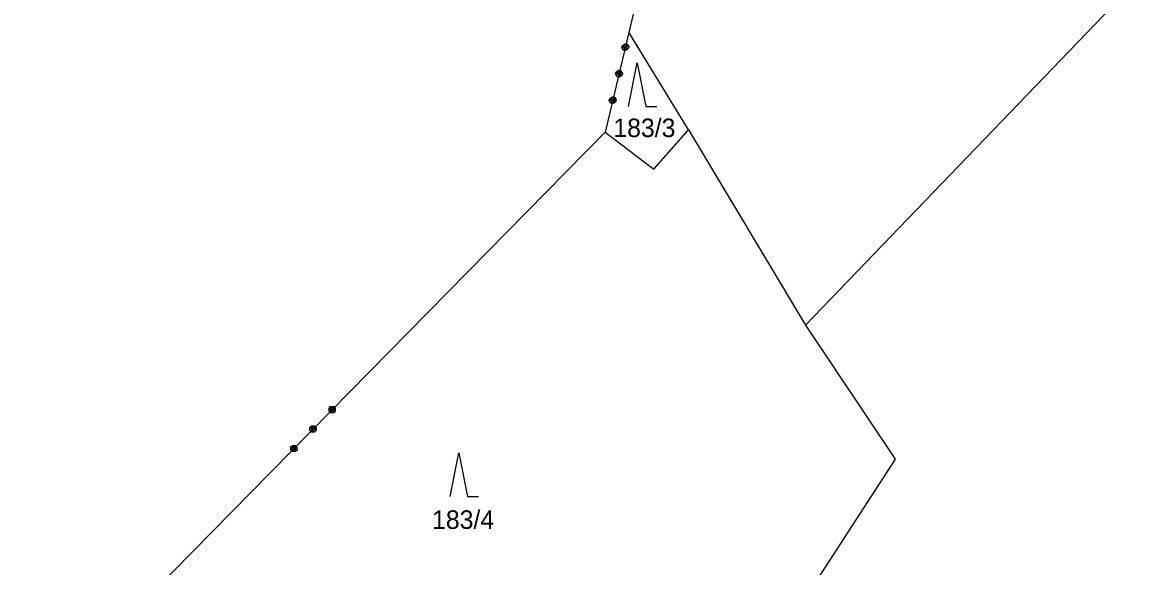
# Model space of a CAD drawing. Extents: x -866656 to -858817, y -1041816 to -1038653.
# Drawn here: x -864815.7 to -864712.3, y -1041085.8 to -1041035.9 of the extents above; entities that cross this region are included whole.
import ezdxf

# ---------------------------------------------------------------- set-up
doc = ezdxf.new("R2010")
doc.units = 0
doc.layers.add('Vrstva 1', color=7, linetype='Continuous')
doc.layers.add('Vrstva 3', color=7, linetype='Continuous')

msp = doc.modelspace()

# ---------------------------------------------------------------- linework, layer by layer
at = {"layer": 'Vrstva 1'}
for p, q in [((-864743.95, -1041063.62), (-864712.34, -1041030.74)), ((-864754.65, -1041045.72), (-864760.13, -1041036.76)), ((-864760.16, -1041043.59), (-864759.36, -1041039.59)), ((-864759.36, -1041039.59), (-864758.56, -1041043.59)), ((-864758.56, -1041043.59), (-864757.56, -1041043.59)), ((-864762.31, -1041045.95), (-864757.85, -1041049.32)), ((-864757.85, -1041049.32), (-864754.65, -1041045.72)), ((-864754.65, -1041045.72), (-864743.95, -1041063.62)), ((-864743.95, -1041063.62), (-864735.74, -1041075.92)), ((-864776.51, -1041079.34), (-864775.71, -1041075.34)), ((-864775.71, -1041075.34), (-864774.91, -1041079.34)), ((-864735.74, -1041075.92), (-864746.95, -1041093.22)), ((-864774.91, -1041079.34), (-864773.91, -1041079.34))]:
    msp.add_line(p, q, dxfattribs=at)
at = {"layer": 'Vrstva 3'}
for p, q in [((-864759.71, -1041035.01), (-864762.31, -1041045.95)), ((-864759.71, -1041035.01), (-864762.31, -1041045.95)), ((-864760.77, -1041038.17), (-864760.72, -1041037.98)), ((-864760.77, -1041038.17), (-864760.72, -1041037.98)), ((-864760.62, -1041038.41), (-864760.77, -1041038.17)), ((-864760.62, -1041038.41), (-864760.77, -1041038.17)), ((-864760.72, -1041037.98), (-864760.48, -1041037.83)), ((-864760.72, -1041037.98), (-864760.48, -1041037.83)), ((-864760.67, -1041038.2), (-864760.63, -1041038)), ((-864760.67, -1041038.2), (-864760.63, -1041038)), ((-864760.28, -1041038.29), (-864760.67, -1041038.2)), ((-864760.28, -1041038.29), (-864760.67, -1041038.2)), ((-864760.65, -1041038.1), (-864760.26, -1041038.19)), ((-864760.65, -1041038.1), (-864760.26, -1041038.19)), ((-864760.63, -1041038), (-864760.24, -1041038.09)), ((-864760.63, -1041038), (-864760.24, -1041038.09)), ((-864760.6, -1041038.32), (-864760.4, -1041038.36)), ((-864760.6, -1041038.32), (-864760.4, -1041038.36)), ((-864760.31, -1041037.97), (-864760.51, -1041037.93)), ((-864760.31, -1041037.97), (-864760.51, -1041037.93)), ((-864760.48, -1041037.83), (-864760.29, -1041037.88)), ((-864760.48, -1041037.83), (-864760.29, -1041037.88)), ((-864760.19, -1041038.31), (-864760.43, -1041038.46)), ((-864760.19, -1041038.31), (-864760.43, -1041038.46)), ((-864760.4, -1041038.36), (-864760.28, -1041038.29)), ((-864760.4, -1041038.36), (-864760.28, -1041038.29)), ((-864760.24, -1041038.09), (-864760.31, -1041037.97)), ((-864760.24, -1041038.09), (-864760.31, -1041037.97)), ((-864760.29, -1041037.88), (-864760.14, -1041038.12)), ((-864760.29, -1041037.88), (-864760.14, -1041038.12)), ((-864760.14, -1041038.12), (-864760.19, -1041038.31)), ((-864760.14, -1041038.12), (-864760.19, -1041038.31)), ((-864760.43, -1041038.46), (-864760.62, -1041038.41)), ((-864760.43, -1041038.46), (-864760.62, -1041038.41)), ((-864761.35, -1041040.6), (-864761.3, -1041040.41)), ((-864761.35, -1041040.6), (-864761.3, -1041040.41)), ((-864761.3, -1041040.41), (-864761.06, -1041040.26)), ((-864761.3, -1041040.41), (-864761.06, -1041040.26)), ((-864761.25, -1041040.63), (-864761.2, -1041040.43)), ((-864761.25, -1041040.63), (-864761.2, -1041040.43)), ((-864761.2, -1041040.43), (-864760.82, -1041040.53)), ((-864761.2, -1041040.43), (-864760.82, -1041040.53)), ((-864760.89, -1041040.41), (-864761.08, -1041040.36)), ((-864760.89, -1041040.41), (-864761.08, -1041040.36)), ((-864761.06, -1041040.26), (-864760.87, -1041040.31)), ((-864761.06, -1041040.26), (-864760.87, -1041040.31)), ((-864760.82, -1041040.53), (-864760.89, -1041040.41)), ((-864760.82, -1041040.53), (-864760.89, -1041040.41)), ((-864760.87, -1041040.31), (-864760.72, -1041040.55)), ((-864760.87, -1041040.31), (-864760.72, -1041040.55)), ((-864761.2, -1041040.85), (-864761.35, -1041040.6)), ((-864761.2, -1041040.85), (-864761.35, -1041040.6)), ((-864760.86, -1041040.72), (-864761.25, -1041040.63)), ((-864760.86, -1041040.72), (-864761.25, -1041040.63)), ((-864761.23, -1041040.53), (-864760.84, -1041040.62)), ((-864761.23, -1041040.53), (-864760.84, -1041040.62)), ((-864761.01, -1041040.89), (-864761.2, -1041040.85)), ((-864761.01, -1041040.89), (-864761.2, -1041040.85)), ((-864761.18, -1041040.75), (-864760.98, -1041040.8)), ((-864761.18, -1041040.75), (-864760.98, -1041040.8)), ((-864760.76, -1041040.74), (-864761.01, -1041040.89)), ((-864760.76, -1041040.74), (-864761.01, -1041040.89)), ((-864760.98, -1041040.8), (-864760.86, -1041040.72)), ((-864760.98, -1041040.8), (-864760.86, -1041040.72)), ((-864760.72, -1041040.55), (-864760.76, -1041040.74)), ((-864760.72, -1041040.55), (-864760.76, -1041040.74)), ((-864761.93, -1041043.04), (-864761.88, -1041042.84)), ((-864761.93, -1041043.04), (-864761.88, -1041042.84)), ((-864761.78, -1041043.28), (-864761.93, -1041043.04)), ((-864761.78, -1041043.28), (-864761.93, -1041043.04)), ((-864761.88, -1041042.84), (-864761.64, -1041042.69)), ((-864761.88, -1041042.84), (-864761.64, -1041042.69)), ((-864761.83, -1041043.06), (-864761.78, -1041042.87)), ((-864761.83, -1041043.06), (-864761.78, -1041042.87)), ((-864761.44, -1041043.15), (-864761.83, -1041043.06)), ((-864761.44, -1041043.15), (-864761.83, -1041043.06)), ((-864761.81, -1041042.96), (-864761.42, -1041043.06)), ((-864761.81, -1041042.96), (-864761.42, -1041043.06)), ((-864761.78, -1041042.87), (-864761.39, -1041042.96)), ((-864761.78, -1041042.87), (-864761.39, -1041042.96)), ((-864761.58, -1041043.32), (-864761.78, -1041043.28)), ((-864761.58, -1041043.32), (-864761.78, -1041043.28)), ((-864761.75, -1041043.18), (-864761.56, -1041043.23)), ((-864761.75, -1041043.18), (-864761.56, -1041043.23)), ((-864761.47, -1041042.84), (-864761.66, -1041042.79)), ((-864761.47, -1041042.84), (-864761.66, -1041042.79)), ((-864761.64, -1041042.69), (-864761.44, -1041042.74)), ((-864761.64, -1041042.69), (-864761.44, -1041042.74)), ((-864761.34, -1041043.18), (-864761.58, -1041043.32)), ((-864761.34, -1041043.18), (-864761.58, -1041043.32)), ((-864761.56, -1041043.23), (-864761.44, -1041043.15)), ((-864761.56, -1041043.23), (-864761.44, -1041043.15)), ((-864761.39, -1041042.96), (-864761.47, -1041042.84)), ((-864761.39, -1041042.96), (-864761.47, -1041042.84)), ((-864761.44, -1041042.74), (-864761.3, -1041042.98)), ((-864761.44, -1041042.74), (-864761.3, -1041042.98)), ((-864761.3, -1041042.98), (-864761.34, -1041043.18)), ((-864761.3, -1041042.98), (-864761.34, -1041043.18)), ((-864762.31, -1041045.95), (-864815.68, -1041100.22)), ((-864762.31, -1041045.95), (-864815.68, -1041100.22)), ((-864787.6, -1041071.23), (-864787.46, -1041071.09)), ((-864787.6, -1041071.23), (-864787.46, -1041071.09)), ((-864787.59, -1041071.52), (-864787.6, -1041071.23)), ((-864787.59, -1041071.52), (-864787.6, -1041071.23)), ((-864787.52, -1041071.3), (-864787.38, -1041071.16)), ((-864787.52, -1041071.3), (-864787.38, -1041071.16)), ((-864787.24, -1041071.59), (-864787.52, -1041071.3)), ((-864787.24, -1041071.59), (-864787.52, -1041071.3)), ((-864787.46, -1041071.09), (-864787.17, -1041071.09)), ((-864787.46, -1041071.09), (-864787.17, -1041071.09)), ((-864787.45, -1041071.23), (-864787.17, -1041071.51)), ((-864787.45, -1041071.23), (-864787.17, -1041071.51)), ((-864787.38, -1041071.16), (-864787.1, -1041071.44)), ((-864787.38, -1041071.16), (-864787.1, -1041071.44)), ((-864787.1, -1041071.3), (-864787.24, -1041071.16)), ((-864787.1, -1041071.3), (-864787.24, -1041071.16)), ((-864787.17, -1041071.09), (-864787.03, -1041071.23)), ((-864787.17, -1041071.09), (-864787.03, -1041071.23)), ((-864787.1, -1041071.44), (-864787.1, -1041071.3)), ((-864787.1, -1041071.44), (-864787.1, -1041071.3)), ((-864787.03, -1041071.23), (-864787.03, -1041071.51)), ((-864787.03, -1041071.23), (-864787.03, -1041071.51)), ((-864787.45, -1041071.66), (-864787.59, -1041071.52)), ((-864787.45, -1041071.66), (-864787.59, -1041071.52)), ((-864787.52, -1041071.45), (-864787.38, -1041071.59)), ((-864787.52, -1041071.45), (-864787.38, -1041071.59)), ((-864787.17, -1041071.66), (-864787.45, -1041071.66)), ((-864787.17, -1041071.66), (-864787.45, -1041071.66)), ((-864787.38, -1041071.59), (-864787.24, -1041071.59)), ((-864787.38, -1041071.59), (-864787.24, -1041071.59)), ((-864787.03, -1041071.51), (-864787.17, -1041071.66)), ((-864787.03, -1041071.51), (-864787.17, -1041071.66)), ((-864789.35, -1041073.02), (-864789.21, -1041072.87)), ((-864789.35, -1041073.02), (-864789.21, -1041072.87)), ((-864789.35, -1041073.3), (-864789.35, -1041073.02)), ((-864789.35, -1041073.3), (-864789.35, -1041073.02)), ((-864789.2, -1041073.44), (-864789.35, -1041073.3)), ((-864789.2, -1041073.44), (-864789.35, -1041073.3)), ((-864789.28, -1041073.09), (-864789.14, -1041072.94)), ((-864789.28, -1041073.09), (-864789.14, -1041072.94)), ((-864788.99, -1041073.37), (-864789.28, -1041073.09)), ((-864788.99, -1041073.37), (-864789.28, -1041073.09)), ((-864789.28, -1041073.23), (-864789.13, -1041073.37)), ((-864789.28, -1041073.23), (-864789.13, -1041073.37)), ((-864789.21, -1041072.87), (-864788.93, -1041072.87)), ((-864789.21, -1041072.87), (-864788.93, -1041072.87)), ((-864789.21, -1041073.02), (-864788.92, -1041073.3)), ((-864789.21, -1041073.02), (-864788.92, -1041073.3)), ((-864788.92, -1041073.44), (-864789.2, -1041073.44)), ((-864788.92, -1041073.44), (-864789.2, -1041073.44)), ((-864789.14, -1041072.94), (-864788.85, -1041073.22)), ((-864789.14, -1041072.94), (-864788.85, -1041073.22)), ((-864789.13, -1041073.37), (-864788.99, -1041073.37)), ((-864789.13, -1041073.37), (-864788.99, -1041073.37)), ((-864788.85, -1041073.08), (-864789, -1041072.94)), ((-864788.85, -1041073.08), (-864789, -1041072.94)), ((-864788.93, -1041072.87), (-864788.78, -1041073.01)), ((-864788.93, -1041072.87), (-864788.78, -1041073.01)), ((-864788.78, -1041073.3), (-864788.92, -1041073.44)), ((-864788.78, -1041073.3), (-864788.92, -1041073.44)), ((-864788.85, -1041073.22), (-864788.85, -1041073.08)), ((-864788.85, -1041073.22), (-864788.85, -1041073.08)), ((-864788.78, -1041073.01), (-864788.78, -1041073.3)), ((-864788.78, -1041073.01), (-864788.78, -1041073.3)), ((-864791.1, -1041074.8), (-864790.96, -1041074.66)), ((-864791.1, -1041074.8), (-864790.96, -1041074.66)), ((-864791.1, -1041075.08), (-864791.1, -1041074.8)), ((-864791.1, -1041075.08), (-864791.1, -1041074.8)), ((-864790.96, -1041075.22), (-864791.1, -1041075.08)), ((-864790.96, -1041075.22), (-864791.1, -1041075.08)), ((-864791.03, -1041074.87), (-864790.89, -1041074.73)), ((-864791.03, -1041074.87), (-864790.89, -1041074.73)), ((-864790.74, -1041075.15), (-864791.03, -1041074.87)), ((-864790.74, -1041075.15), (-864791.03, -1041074.87)), ((-864791.03, -1041075.01), (-864790.89, -1041075.15)), ((-864791.03, -1041075.01), (-864790.89, -1041075.15)), ((-864790.96, -1041074.66), (-864790.68, -1041074.65)), ((-864790.96, -1041074.66), (-864790.68, -1041074.65)), ((-864790.96, -1041074.8), (-864790.68, -1041075.08)), ((-864790.96, -1041074.8), (-864790.68, -1041075.08)), ((-864790.67, -1041075.22), (-864790.96, -1041075.22)), ((-864790.67, -1041075.22), (-864790.96, -1041075.22)), ((-864790.89, -1041074.73), (-864790.6, -1041075.01)), ((-864790.89, -1041074.73), (-864790.6, -1041075.01)), ((-864790.89, -1041075.15), (-864790.74, -1041075.15)), ((-864790.89, -1041075.15), (-864790.74, -1041075.15)), ((-864790.61, -1041074.87), (-864790.75, -1041074.73)), ((-864790.61, -1041074.87), (-864790.75, -1041074.73)), ((-864790.68, -1041074.65), (-864790.54, -1041074.8)), ((-864790.68, -1041074.65), (-864790.54, -1041074.8)), ((-864790.53, -1041075.08), (-864790.67, -1041075.22)), ((-864790.53, -1041075.08), (-864790.67, -1041075.22)), ((-864790.6, -1041075.01), (-864790.61, -1041074.87)), ((-864790.6, -1041075.01), (-864790.61, -1041074.87)), ((-864790.54, -1041074.8), (-864790.53, -1041075.08)), ((-864790.54, -1041074.8), (-864790.53, -1041075.08))]:
    msp.add_line(p, q, dxfattribs=at)

# ---------------------------------------------------------------- texts
at = {"layer": 'Vrstva 1'}
for s, p in [('183/3', (-864761.55, -1041046.39)), ('183/4', (-864778.16, -1041082.31))]:
    msp.add_text(s, height=1.7, dxfattribs=at).set_placement(p)

doc.saveas('drawing.dxf')
